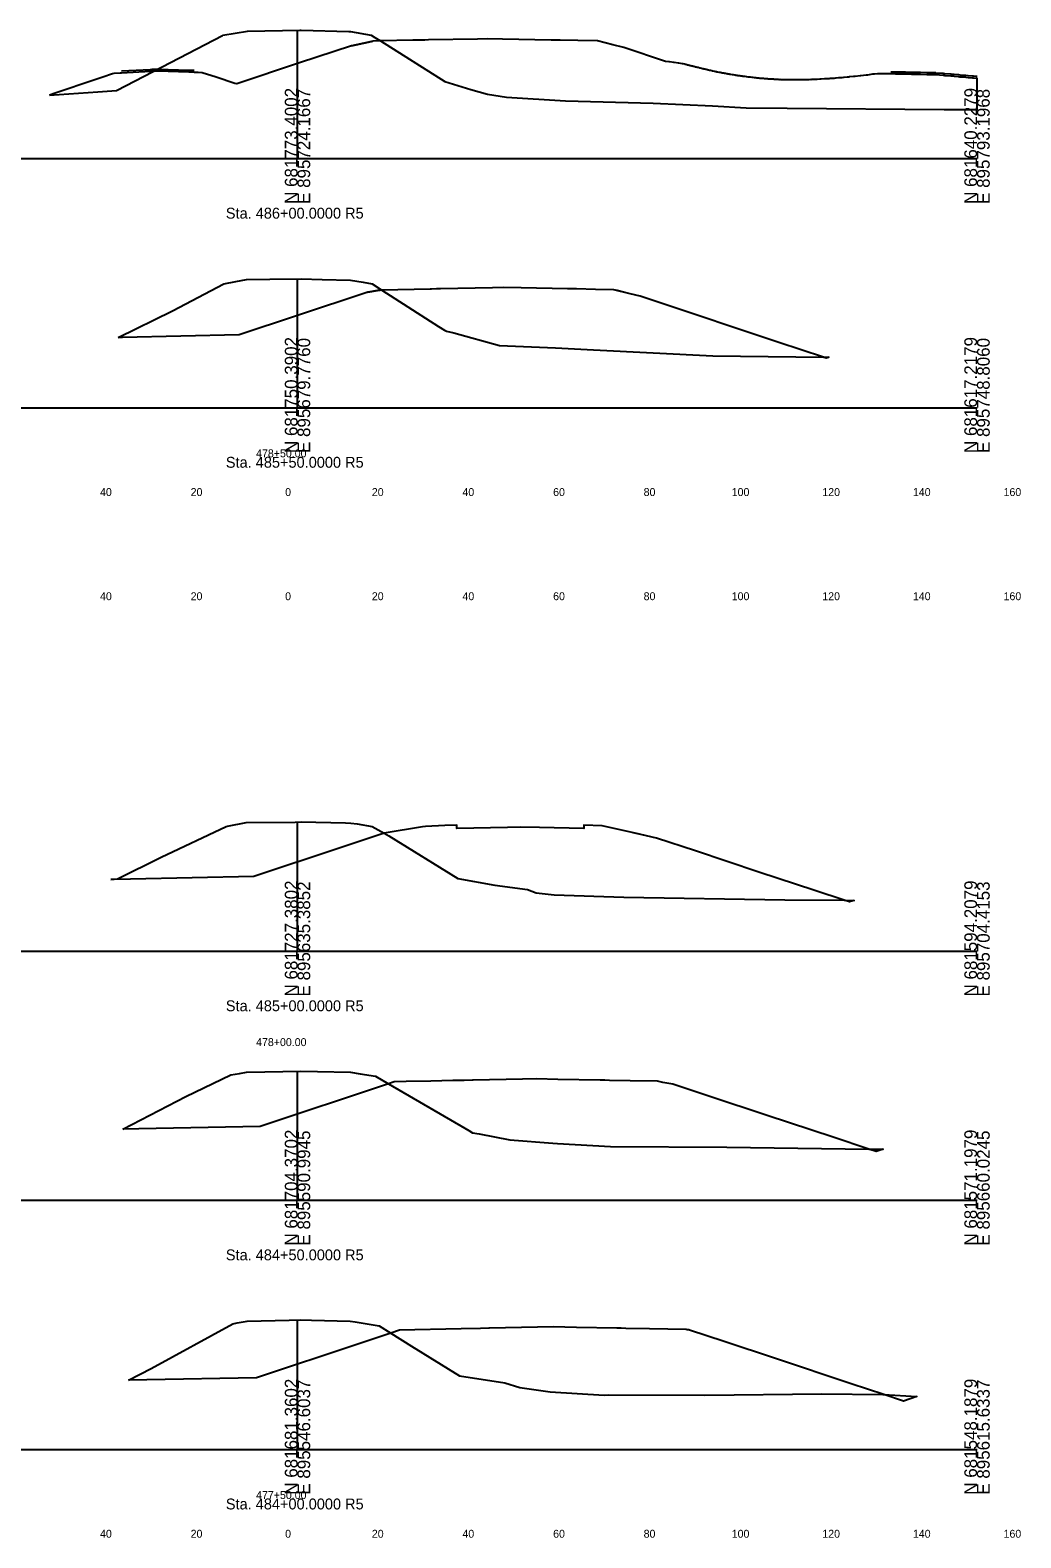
# Model space of a CAD drawing. Extents: x 21059 to 22955, y 6470 to 17494.
# Drawn here: x 21585.8 to 21804.5, y 11995.3 to 12328.2 of the extents above; entities that cross this region are included whole.
import ezdxf

# ---------------------------------------------------------------- set-up
doc = ezdxf.new("R2010")
doc.units = 0
for name, color, linetype in [('Draft_XS_Text', 7, 'Continuous'), ('DTM CONTOURS_MAJOR', 7, 'Continuous'), ('SLOPE_STAKES_FILL', 7, 'Continuous'), ('X_PROFILES_1', 7, 'Continuous'), ('XS_M_SHAPES_EARTHWORK', 7, 'Continuous'), ('XS_P_GROUND_B', 7, 'Continuous'), ('XS_P_TX_CLEARZONE', 7, 'Continuous'), ('XS_SHEET_EW_TX_VOLUME', 7, 'Continuous')]:
    doc.layers.add(name, color=color, linetype=linetype)

msp = doc.modelspace()

# ---------------------------------------------------------------- linework, layer by layer
at = {"layer": 'DTM CONTOURS_MAJOR'}
for p, q in [((21644.84, 12299.84), (21644.84, 12328.2)), ((21494.84, 12299.84), (21644.84, 12299.84)), ((21644.84, 12299.84), (21794.84, 12299.84)), ((21644.84, 12244.84), (21644.84, 12273.31)), ((21494.84, 12244.84), (21644.84, 12244.84)), ((21644.84, 12244.84), (21794.84, 12244.84)), ((21644.84, 12124.84), (21644.84, 12153.39)), ((21494.84, 12124.84), (21644.84, 12124.84)), ((21644.84, 12124.84), (21794.84, 12124.84)), ((21644.84, 12069.84), (21644.84, 12098.38)), ((21494.84, 12069.84), (21644.84, 12069.84)), ((21644.84, 12069.84), (21794.84, 12069.84)), ((21644.84, 12014.84), (21644.84, 12043.43)), ((21494.84, 12014.84), (21644.84, 12014.84)), ((21644.84, 12014.84), (21794.84, 12014.84))]:
    msp.add_line(p, q, dxfattribs=at)
at = {"layer": 'XS_M_SHAPES_EARTHWORK'}
msp.add_lwpolyline([(21605.99, 12319.23), (21612.39, 12319.54), (21612.77, 12319.56), (21614.03, 12319.62), (21620.87, 12319.4), (21622.06, 12319.36)], dxfattribs=at)
at = {"layer": 'XS_P_TX_CLEARZONE'}
for points in [[(21656.73, 12324.76), (21660.52, 12325.58), (21661.44, 12325.78)], [(21656.73, 12324.76), (21660.52, 12325.58), (21661.44, 12325.78)], [(21716.88, 12324.35), (21714.47, 12324.95), (21711.04, 12325.81)], [(21716.88, 12324.35), (21714.47, 12324.95), (21711.04, 12325.81)], [(21605.99, 12319.23), (21612.4, 12319.54), (21612.77, 12319.56), (21614.03, 12319.62), (21620.87, 12319.4), (21622.06, 12319.36)], [(21775.85, 12319.03), (21776.82, 12319.01), (21777.39, 12319), (21777.71, 12318.99), (21778.6, 12318.97), (21779.05, 12318.97), (21779.72, 12318.95), (21780.38, 12318.94), (21780.72, 12318.93), (21781.73, 12318.91), (21782.17, 12318.9), (21782.38, 12318.9), (21783.75, 12318.87), (21783.95, 12318.87), (21784.05, 12318.86), (21785.52, 12318.83), (21785.72, 12318.82), (21785.73, 12318.82), (21785.76, 12318.81), (21787.38, 12318.67), (21787.51, 12318.66), (21787.77, 12318.64), (21789.05, 12318.53), (21789.3, 12318.51), (21789.79, 12318.47), (21790.72, 12318.39), (21791.08, 12318.35), (21791.8, 12318.29), (21792.38, 12318.24), (21792.86, 12318.2), (21793.81, 12318.12), (21794.05, 12318.1), (21794.64, 12318.05), (21794.84, 12318.03)], [(21660.34, 12270.35), (21662.52, 12270.73), (21663.07, 12270.83)], [(21660.34, 12270.35), (21662.52, 12270.73), (21663.07, 12270.83)], [(21720.5, 12269.44), (21718.25, 12270), (21714.65, 12270.89)], [(21720.5, 12269.44), (21718.25, 12270), (21714.65, 12270.89)], [(21724.11, 12149.81), (21720.91, 12150.53), (21718.95, 12150.98)], [(21724.11, 12149.81), (21720.91, 12150.53), (21718.95, 12150.98)], [(21727.72, 12095.48), (21725.49, 12095.88), (21724.31, 12096.11)], [(21727.72, 12095.48), (21725.49, 12095.88), (21724.31, 12096.11)], [(21731.34, 12041.18), (21730.89, 12041.26), (21730.63, 12041.3)], [(21731.34, 12041.18), (21730.89, 12041.26), (21730.63, 12041.3)]]:
    msp.add_lwpolyline(points, dxfattribs=at)
at = {"layer": 'XS_SHEET_EW_TX_VOLUME'}
for points in [[(21612.99, 12319.07), (21624.43, 12325.01), (21628.29, 12327.05), (21628.38, 12327.07), (21633.77, 12328), (21645.39, 12328.2), (21645.67, 12328.2), (21656.14, 12327.92), (21656.44, 12327.91), (21656.57, 12327.89), (21661.11, 12327.12), (21661.92, 12326.59), (21663.16, 12325.81), (21661.44, 12325.78), (21660.52, 12325.58), (21656.73, 12324.76), (21645.3, 12320.96), (21631.43, 12316.33), (21631.11, 12316.43), (21631.03, 12316.46), (21626.85, 12317.81), (21623.78, 12318.81), (21622.91, 12318.84), (21622.06, 12318.86), (21620.87, 12318.9), (21614.03, 12319.12)], [(21663.16, 12325.81), (21677.33, 12316.9), (21683.08, 12315.1), (21686.8, 12314.09), (21690.97, 12313.41), (21704.02, 12312.57), (21723.35, 12312.08), (21736.46, 12311.46), (21743.86, 12311.07), (21752.96, 12310.98), (21787.59, 12310.65), (21794.84, 12310.7), (21794.84, 12317.53), (21794.64, 12317.55), (21794.05, 12317.6), (21793.81, 12317.62), (21792.86, 12317.7), (21792.38, 12317.74), (21791.8, 12317.79), (21791.08, 12317.85), (21790.72, 12317.89), (21789.79, 12317.97), (21789.3, 12318.01), (21789.05, 12318.03), (21787.77, 12318.14), (21787.51, 12318.16), (21787.38, 12318.17), (21785.76, 12318.31), (21785.73, 12318.32), (21785.72, 12318.32), (21785.52, 12318.33), (21784.05, 12318.36), (21783.95, 12318.37), (21783.75, 12318.37), (21782.38, 12318.4), (21782.17, 12318.4), (21781.73, 12318.41), (21780.72, 12318.43), (21780.38, 12318.44), (21779.72, 12318.45), (21779.05, 12318.47), (21778.6, 12318.47), (21777.71, 12318.49), (21777.39, 12318.5), (21776.82, 12318.51), (21775.85, 12318.53), (21775.75, 12318.53), (21775.71, 12318.53), (21775.19, 12318.54), (21775.04, 12318.55), (21774.45, 12318.56), (21773.93, 12318.57), (21773.73, 12318.57), (21773.26, 12318.58), (21773.21, 12318.58), (21772.9, 12318.59), (21772.85, 12318.59), (21772.85, 12318.59), (21772.23, 12318.5), (21772.19, 12318.5), (21771.78, 12318.45), (21771.75, 12318.45), (21770.67, 12318.3), (21770.57, 12318.29), (21770.37, 12318.27), (21770.35, 12318.27), (21769.18, 12318.12), (21769.04, 12318.11), (21769.03, 12318.12), (21769.03, 12318.12), (21767.93, 12317.98), (21767.77, 12317.98), (21767.61, 12317.96), (21767.59, 12317.96), (21766.71, 12317.86), (21766.56, 12317.85), (21766.26, 12317.82), (21766.21, 12317.82), (21765.54, 12317.74), (21765.4, 12317.74), (21764.98, 12317.7), (21764.89, 12317.7), (21764.4, 12317.65), (21764.28, 12317.65), (21764.26, 12317.64), (21764.25, 12317.64), (21763.75, 12317.59), (21763.63, 12317.59), (21763.3, 12317.56), (21763.21, 12317.56), (21762.6, 12317.5), (21762.42, 12317.5), (21762.23, 12317.48), (21762.18, 12317.49), (21761.49, 12317.42), (21761.26, 12317.42), (21761.2, 12317.42), (21761.18, 12317.42), (21760.47, 12317.36), (21760.22, 12317.37), (21760.17, 12317.37), (21760.15, 12317.37), (21759.54, 12317.31), (21759.29, 12317.32), (21759.15, 12317.31), (21759.09, 12317.32), (21758.72, 12317.29), (21758.57, 12317.3), (21758.44, 12317.29), (21758.39, 12317.29), (21758.16, 12317.27), (21758.06, 12317.28), (21757.69, 12317.25), (21757.52, 12317.26), (21757.22, 12317.24), (21757.07, 12317.25), (21756.85, 12317.24), (21756.74, 12317.25), (21756.33, 12317.22), (21756.11, 12317.23), (21755.94, 12317.22), (21755.85, 12317.23), (21755.43, 12317.2), (21755.18, 12317.22), (21755.14, 12317.22), (21755.12, 12317.23), (21754.8, 12317.25), (21754.29, 12317.21), (21754.28, 12317.22), (21754.28, 12317.22), (21754.02, 12317.21), (21753.85, 12317.22), (21753.66, 12317.21), (21753.53, 12317.23), (21753.46, 12317.22), (21753.42, 12317.23), (21753.05, 12317.21), (21752.79, 12317.24), (21752.67, 12317.23), (21752.58, 12317.24), (21752.29, 12317.23), (21752.07, 12317.25), (21751.89, 12317.25), (21751.76, 12317.26), (21751.54, 12317.26), (21751.37, 12317.28), (21751.15, 12317.27), (21750.96, 12317.29), (21750.81, 12317.29), (21750.69, 12317.3), (21750.45, 12317.33), (21750.18, 12317.32), (21750.12, 12317.33), (21750.07, 12317.34), (21749.94, 12317.36), (21749.8, 12317.35), (21749.62, 12317.37), (21749.42, 12317.36), (21749.4, 12317.36), (21749.37, 12317.37), (21749.04, 12317.37), (21748.73, 12317.41), (21748.71, 12317.41), (21748.69, 12317.42), (21748.39, 12317.46), (21748.1, 12317.46), (21748.03, 12317.46), (21747.96, 12317.47), (21747.72, 12317.51), (21747.49, 12317.51), (21747.38, 12317.51), (21747.26, 12317.53), (21747.06, 12317.56), (21746.88, 12317.56), (21746.71, 12317.59), (21746.57, 12317.59), (21746.46, 12317.59), (21746.33, 12317.62), (21746.28, 12317.62), (21746.23, 12317.62), (21746.04, 12317.65), (21745.89, 12317.65), (21745.83, 12317.65), (21745.75, 12317.67), (21745.46, 12317.72), (21745.23, 12317.72), (21745.2, 12317.72), (21745.18, 12317.74), (21744.83, 12317.79), (21744.57, 12317.79), (21744.57, 12317.79), (21744.57, 12317.8), (21744.35, 12317.8), (21744.06, 12317.87), (21743.98, 12317.88), (21743.93, 12317.88), (21743.66, 12317.94), (21743.47, 12317.94), (21743.4, 12317.94), (21743.3, 12317.96), (21743.18, 12317.97), (21742.99, 12318.01), (21742.98, 12318.01), (21742.97, 12318.01), (21742.8, 12318.05), (21742.68, 12318.05), (21742.51, 12318.09), (21742.39, 12318.09), (21742.2, 12318.13), (21742.07, 12318.14), (21741.94, 12318.17), (21741.87, 12318.17), (21741.62, 12318.22), (21741.47, 12318.23), (21741.42, 12318.23), (21741.35, 12318.25), (21741.05, 12318.32), (21740.88, 12318.32), (21740.86, 12318.32), (21740.83, 12318.33), (21740.51, 12318.41), (21740.32, 12318.42), (21740.31, 12318.42), (21740.29, 12318.43), (21740.1, 12318.48), (21740, 12318.48), (21739.91, 12318.51), (21739.86, 12318.51), (21739.76, 12318.53), (21739.71, 12318.53), (21739.48, 12318.59), (21739.36, 12318.6), (21739.21, 12318.63), (21739.13, 12318.63), (21738.93, 12318.69), (21738.83, 12318.69), (21738.65, 12318.74), (21738.57, 12318.74), (21738.41, 12318.78), (21738.34, 12318.79), (21738.11, 12318.84), (21738, 12318.85), (21737.97, 12318.85), (21737.89, 12318.88), (21737.59, 12318.95), (21737.45, 12318.96), (21737.42, 12318.96), (21737.37, 12318.98), (21737.23, 12319.02), (21737.17, 12319.02), (21736.98, 12319.07), (21736.89, 12319.07), (21736.89, 12319.08), (21736.89, 12319.08), (21736.56, 12319.17), (21736.41, 12319.18), (21736.39, 12319.19), (21736.34, 12319.2), (21736.06, 12319.28), (21735.94, 12319.29), (21735.84, 12319.32), (21735.8, 12319.32), (21735.56, 12319.39), (21735.46, 12319.39), (21735.32, 12319.44), (21735.25, 12319.44), (21735.07, 12319.49), (21734.99, 12319.5), (21734.79, 12319.56), (21734.71, 12319.56), (21734.58, 12319.6), (21734.53, 12319.61), (21734.47, 12319.63), (21734.44, 12319.63), (21734.25, 12319.68), (21734.17, 12319.69), (21734.15, 12319.69), (21734.1, 12319.72), (21733.77, 12319.81), (21733.63, 12319.82), (21733.63, 12319.82), (21733.63, 12319.83), (21733.27, 12319.93), (21733.13, 12319.95), (21733.12, 12319.95), (21733.1, 12319.96), (21732.81, 12320.05), (21732.7, 12320.06), (21732.6, 12320.09), (21732.56, 12320.09), (21732.3, 12320.17), (21732.2, 12320.18), (21732.08, 12320.22), (21732.03, 12320.22), (21731.84, 12320.28), (21731.76, 12320.29), (21731.75, 12320.29), (21731.74, 12320.29), (21731.56, 12320.35), (21731.49, 12320.36), (21731.34, 12320.41), (21731.28, 12320.41), (21731.05, 12320.48), (21730.96, 12320.49), (21730.85, 12320.53), (21730.81, 12320.53), (21730.53, 12320.62), (21730.43, 12320.63), (21730.4, 12320.64), (21730.35, 12320.66), (21730.01, 12320.76), (21729.89, 12320.77), (21729.88, 12320.77), (21729.87, 12320.78), (21729.86, 12320.78), (21729.86, 12320.79), (21729.02, 12320.9), (21728.91, 12320.91), (21727.99, 12321.04), (21727.91, 12321.05), (21726.95, 12321.18), (21726.91, 12321.18), (21726.08, 12321.29), (21716.88, 12324.35), (21714.45, 12324.96), (21714.45, 12324.96), (21714.45, 12324.96), (21714.45, 12324.96), (21714.44, 12324.96), (21711.04, 12325.81), (21706.75, 12325.89), (21702.85, 12325.97), (21701.65, 12325.99), (21700.84, 12326.01), (21690.12, 12326.22), (21686.8, 12326.29), (21684.61, 12326.24), (21673.74, 12326.03), (21672.93, 12326.01), (21672.77, 12326.01), (21670.85, 12325.97), (21670.76, 12325.97), (21670.31, 12325.96)], [(21590.09, 12313.83), (21600.77, 12314.6), (21604.86, 12314.85), (21612.99, 12319.07), (21612.77, 12319.06), (21612.39, 12319.04), (21605.99, 12318.73), (21605.69, 12318.72), (21604.28, 12318.65), (21604.27, 12318.65), (21603.97, 12318.55), (21601.88, 12317.84), (21597.64, 12316.39), (21593.76, 12315.07), (21591.6, 12314.34), (21591.37, 12314.26), (21590.09, 12313.83)], [(21605.23, 12260.34), (21617.25, 12266.24), (21628.59, 12272.21), (21631.23, 12272.73), (21633.6, 12273.14), (21638.71, 12273.23), (21645.68, 12273.3), (21650.32, 12273.18), (21656.53, 12273.03), (21659.32, 12272.57), (21661.34, 12272.22), (21663.48, 12270.83), (21663.07, 12270.83), (21662.52, 12270.73), (21660.34, 12270.35), (21644.62, 12265.11), (21631.98, 12260.9), (21606.19, 12260.36)], [(21663.48, 12270.83), (21675.95, 12262.75), (21677.26, 12261.93), (21677.75, 12261.77), (21679.35, 12261.34), (21689.46, 12258.56), (21701.82, 12258.05), (21710.2, 12257.65), (21736.5, 12256.26), (21760.92, 12256.01), (21751.1, 12259.27), (21744.91, 12261.33), (21729.56, 12266.43), (21720.5, 12269.44), (21718.25, 12270), (21717.1, 12270.29), (21717.09, 12270.29), (21715.37, 12270.71), (21714.65, 12270.89), (21710.6, 12270.97), (21706.46, 12271.06), (21705.31, 12271.08), (21704.45, 12271.1), (21694.19, 12271.3), (21690.42, 12271.37), (21687.91, 12271.32), (21676.38, 12271.09), (21676.36, 12271.09), (21675.55, 12271.08), (21674.41, 12271.05), (21674.38, 12271.05), (21674.15, 12271.05)], [(21760.92, 12256.01), (21762.14, 12255.99), (21761.54, 12255.8)], [(21603.6, 12140.67), (21605.14, 12140.84), (21614.78, 12145.57), (21629.06, 12152.37), (21629.4, 12152.44), (21633.48, 12153.23), (21644.32, 12153.35), (21645.67, 12153.38), (21655.41, 12153.16), (21656.59, 12153.13), (21657.98, 12152.93), (21661.32, 12152.37), (21663.99, 12150.89), (21663.95, 12150.88), (21654.5, 12147.73), (21635.2, 12141.3), (21607.99, 12140.76)], [(21663.99, 12150.89), (21665, 12150.33), (21680.21, 12140.9), (21688.38, 12139.42), (21695.59, 12138.5), (21697.5, 12137.73), (21701.47, 12137.29), (21716.85, 12136.76), (21752.42, 12136.21), (21765.54, 12136.08), (21759.04, 12138.23), (21746.71, 12142.32), (21732.67, 12146.97), (21724.11, 12149.81), (21719.37, 12150.89), (21712.08, 12152.53), (21708.07, 12152.69), (21708.07, 12152.36), (21708.07, 12151.94), (21698.26, 12152.13), (21694.03, 12152.22), (21691.22, 12152.16), (21679.99, 12151.94), (21679.99, 12152.66), (21679.99, 12152.69), (21677.35, 12152.58), (21673.11, 12152.41), (21672.45, 12152.3)], [(21765.54, 12136.08), (21767.71, 12136.05), (21766.66, 12135.71)], [(21606.26, 12085.54), (21620.21, 12092.77), (21630.15, 12097.51), (21632.06, 12097.86), (21633.58, 12098.16), (21637.61, 12098.2), (21645.59, 12098.38), (21649.25, 12098.3), (21656.51, 12098.11), (21658.67, 12097.8), (21662.06, 12097.25), (21664.92, 12095.58), (21636.57, 12086.13), (21609.79, 12085.61)], [(21664.92, 12095.58), (21681.76, 12085.76), (21682.69, 12085.24), (21683.46, 12084.76), (21684.95, 12084.49), (21691.71, 12083.22), (21701.22, 12082.45), (21702.25, 12082.36), (21713.91, 12081.71), (21739.62, 12081.59), (21770.93, 12081.16), (21763.09, 12083.76), (21748.51, 12088.59), (21735.85, 12092.78), (21727.72, 12095.48), (21725.49, 12095.88), (21724.31, 12096.11), (21718.26, 12096.22), (21713.69, 12096.31), (21712.65, 12096.33), (21711.68, 12096.35), (21702.34, 12096.54), (21697.65, 12096.63), (21694.53, 12096.57), (21683.61, 12096.35), (21683.48, 12096.34), (21681.6, 12096.31), (21679.15, 12096.26), (21674.24, 12096.16), (21668.85, 12096.05), (21666.16, 12095.99)], [(21770.93, 12081.16), (21774.1, 12081.12), (21772.58, 12080.61)], [(21607.54, 12030.09), (21612.55, 12032.68), (21630.6, 12042.59), (21631.49, 12042.76), (21633.71, 12043.18), (21643.03, 12043.38), (21645.61, 12043.43), (21647.96, 12043.37), (21656.49, 12043.15), (21657.59, 12042.99), (21662.86, 12042.14), (21665.42, 12040.52), (21658.37, 12038.17), (21635.8, 12030.63), (21611.6, 12030.17)], [(21665.42, 12040.52), (21669.97, 12037.64), (21680.62, 12031.09), (21690.59, 12029.56), (21693.93, 12028.53), (21700.65, 12027.56), (21712.56, 12026.84), (21713.47, 12026.87), (21734.73, 12026.81), (21760.59, 12027.11), (21774.03, 12026.97), (21774.25, 12026.96), (21767.09, 12029.33), (21750.32, 12034.89), (21739, 12038.64), (21731.34, 12041.18), (21731.19, 12041.21), (21730.89, 12041.26), (21730.63, 12041.3), (21722.55, 12041.46), (21717.3, 12041.56), (21716.32, 12041.58), (21715.3, 12041.6), (21706.41, 12041.77), (21701.26, 12041.87), (21697.84, 12041.8), (21687.22, 12041.59), (21687.05, 12041.58), (21685.22, 12041.55), (21680.96, 12041.46), (21667.39, 12041.18)], [(21774.25, 12026.96), (21781.53, 12026.49), (21778.59, 12025.52)]]:
    msp.add_lwpolyline(points, close=True, dxfattribs=at)

# ---------------------------------------------------------------- texts
at = {"layer": 'Draft_XS_Text'}
for s, p in [('  40  ', (21599.95, 12225.34)), ('  20  ', (21619.95, 12225.34)), ('  0  ', (21640.81, 12225.34)), ('  0  ', (21640.81, 12225.34)), ('  20  ', (21659.95, 12225.34)), ('  40  ', (21679.95, 12225.34)), ('  60  ', (21699.97, 12225.34)), ('  80  ', (21719.95, 12225.34)), ('  100  ', (21739.39, 12225.34)), ('  120  ', (21759.39, 12225.34)), ('  140  ', (21779.39, 12225.34)), ('  160  ', (21799.4, 12225.34)), ('  40  ', (21599.95, 12202.34)), ('  20  ', (21619.95, 12202.34)), ('  0  ', (21640.81, 12202.34)), ('  0  ', (21640.81, 12202.34)), ('  20  ', (21659.95, 12202.34)), ('  40  ', (21679.95, 12202.34)), ('  60  ', (21699.97, 12202.34)), ('  80  ', (21719.95, 12202.34)), ('  100  ', (21739.39, 12202.34)), ('  120  ', (21759.39, 12202.34)), ('  140  ', (21779.39, 12202.34)), ('  160  ', (21799.4, 12202.34)), ('  40  ', (21599.95, 11995.34)), ('  20  ', (21619.95, 11995.34)), ('  0  ', (21640.81, 11995.34)), ('  0  ', (21640.81, 11995.34)), ('  20  ', (21659.95, 11995.34)), ('  40  ', (21679.95, 11995.34)), ('  60  ', (21699.97, 11995.34)), ('  80  ', (21719.95, 11995.34)), ('  100  ', (21739.39, 11995.34)), ('  120  ', (21759.39, 11995.34)), ('  140  ', (21779.39, 11995.34)), ('  160  ', (21799.4, 11995.34))]:
    msp.add_text(s, height=1.75, dxfattribs=at).set_placement(p)
at = {"layer": 'DTM CONTOURS_MAJOR'}
for s, p in [('N 681773.4002', (21644.84, 12289.84)), ('E 895724.1667', (21647.64, 12289.84)), ('N 681640.2279', (21794.84, 12289.84)), ('E 895793.1968', (21797.64, 12289.84)), ('N 681750.3902', (21644.84, 12234.84)), ('E 895679.7760', (21647.64, 12234.84)), ('N 681617.2179', (21794.84, 12234.84)), ('E 895748.8060', (21797.64, 12234.84)), ('N 681727.3802', (21644.84, 12114.84)), ('E 895635.3852', (21647.64, 12114.84)), ('N 681594.2079', (21794.84, 12114.84)), ('E 895704.4153', (21797.64, 12114.84)), ('N 681704.3702', (21644.84, 12059.84)), ('E 895590.9945', (21647.64, 12059.84)), ('N 681571.1979', (21794.84, 12059.84)), ('E 895660.0245', (21797.64, 12059.84)), ('N 681681.3602', (21644.84, 12004.84)), ('E 895546.6037', (21647.64, 12004.84)), ('N 681548.1879', (21794.84, 12004.84)), ('E 895615.6337', (21797.64, 12004.84))]:
    msp.add_text(s, height=2.8, rotation=90, dxfattribs=at).set_placement(p)
at = {"layer": 'SLOPE_STAKES_FILL'}
for s, p in [('  478+50.00  ', (21634.4, 12233.89)), ('  478+00.00  ', (21634.4, 12103.89)), ('  477+50.00  ', (21634.4, 12003.89))]:
    msp.add_text(s, height=1.75, dxfattribs=at).set_placement(p)
at = {"layer": 'X_PROFILES_1'}
for s, p in [('Sta. 486+00.0000 R5', (21629.02, 12286.59)), ('Sta. 485+50.0000 R5', (21629.02, 12231.59)), ('Sta. 485+00.0000 R5', (21629.02, 12111.59)), ('Sta. 484+50.0000 R5', (21629.02, 12056.59)), ('Sta. 484+00.0000 R5', (21629.02, 12001.59))]:
    msp.add_text(s, height=2.4, dxfattribs=at).set_placement(p)
at = {"layer": 'XS_P_GROUND_B'}
for p in [(21628.8, 12315.41), (21628.8, 12315.41), (21757.36, 12310.83), (21757.36, 12310.83), (21631.94, 12260.84), (21631.94, 12260.84), (21761.51, 12255.74), (21761.51, 12255.74), (21635.16, 12141.24), (21635.16, 12141.24), (21766.62, 12135.65), (21766.62, 12135.65), (21636.53, 12086.07), (21636.53, 12086.07), (21772.54, 12080.55), (21772.54, 12080.55), (21635.76, 12030.57), (21635.76, 12030.57), (21778.56, 12025.46), (21778.56, 12025.46)]:
    msp.add_text('X', height=0.12, dxfattribs=at).set_placement(p)

doc.saveas('drawing.dxf')
